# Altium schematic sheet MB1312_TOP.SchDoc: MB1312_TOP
size A4; DocumentNumber: MB1312; Revision: A-03; SheetNumber: 2; SheetTotal: 9; Project: NUCLEO-L4P5ZG
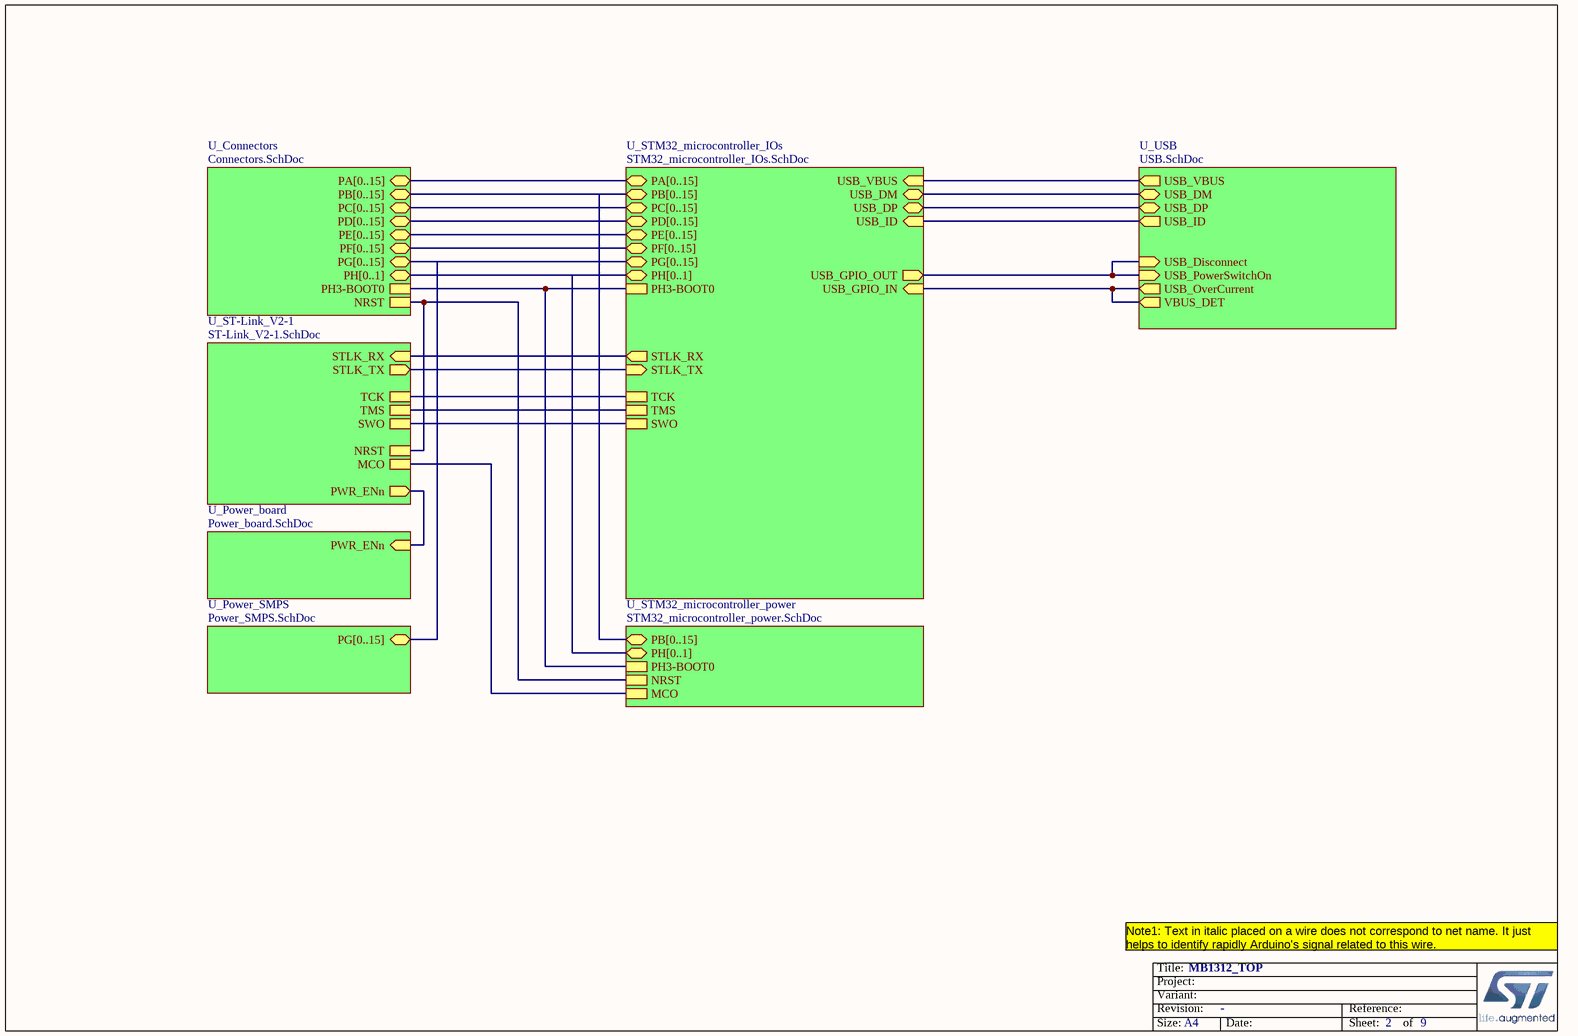
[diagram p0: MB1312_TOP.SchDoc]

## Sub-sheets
U_Connectors = Connectors.SchDoc: PA[0..15] (bidir), PB[0..15] (bidir), PC[0..15] (bidir), NRST, PH3-BOOT0, PD[0..15] (bidir), PE[0..15] (bidir), PF[0..15] (bidir), PG[0..15] (bidir), PH[0..1] (bidir)
U_Power_board = Power_board.SchDoc: PWR_ENn (in)
U_Power_SMPS = Power_SMPS.SchDoc: PG[0..15] (bidir)
U_ST-Link_V2-1 = ST-Link_V2-1.SchDoc: TMS, TCK, MCO, NRST, STLK_RX (in), STLK_TX (out), SWO, PWR_ENn (out)
U_STM32_microcontroller_IOs = STM32_microcontroller_IOs.SchDoc: STLK_TX (in), STLK_RX (out), PA[0..15] (bidir), PB[0..15] (bidir), PC[0..15] (bidir), TCK, TMS, SWO, PD[0..15] (bidir), PE[0..15] (bidir), PF[0..15] (bidir), PG[0..15] (bidir), PH[0..1] (bidir), USB_DM (bidir), USB_DP (bidir), USB_GPIO_OUT (out), USB_GPIO_IN (in), USB_ID (in), USB_VBUS (in), PH3-BOOT0
U_STM32_microcontroller_power = STM32_microcontroller_power.SchDoc: NRST, MCO, PB[0..15] (bidir), PH3-BOOT0, PH[0..1] (bidir)
U_USB = USB.SchDoc: USB_PowerSwitchOn (in), USB_OverCurrent (out), USB_DM (bidir), USB_DP (bidir), USB_ID (out), USB_VBUS (out), USB_Disconnect (in), VBUS_DET (out)

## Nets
(unnamed): sheet U_Connectors/NRST, sheet U_ST-Link_V2-1/NRST, sheet U_STM32_microcontroller_power/NRST
(unnamed): sheet U_Connectors/PH3-BOOT0, sheet U_STM32_microcontroller_IOs/PH3-BOOT0, sheet U_STM32_microcontroller_power/PH3-BOOT0  [a separate net that carries the same name]
(unnamed): sheet U_ST-Link_V2-1/TMS, sheet U_STM32_microcontroller_IOs/TMS  [a separate net that carries the same name]
(unnamed): sheet U_ST-Link_V2-1/TCK, sheet U_STM32_microcontroller_IOs/TCK  [a separate net that carries the same name]
(unnamed): sheet U_ST-Link_V2-1/MCO, sheet U_STM32_microcontroller_power/MCO  [a separate net that carries the same name]
(unnamed): sheet U_ST-Link_V2-1/STLK_RX, sheet U_STM32_microcontroller_IOs/STLK_RX  [a separate net that carries the same name]
(unnamed): sheet U_ST-Link_V2-1/STLK_TX, sheet U_STM32_microcontroller_IOs/STLK_TX  [a separate net that carries the same name]
(unnamed): sheet U_ST-Link_V2-1/SWO, sheet U_STM32_microcontroller_IOs/SWO  [a separate net that carries the same name]
(unnamed): sheet U_ST-Link_V2-1/PWR_ENn, sheet U_Power_board/PWR_ENn  [a separate net that carries the same name]
(unnamed): sheet U_USB/USB_PowerSwitchOn, sheet U_USB/USB_Disconnect, sheet U_STM32_microcontroller_IOs/USB_GPIO_OUT  [a separate net that carries the same name]
(unnamed): sheet U_USB/USB_OverCurrent, sheet U_USB/VBUS_DET, sheet U_STM32_microcontroller_IOs/USB_GPIO_IN  [a separate net that carries the same name]
(unnamed): sheet U_USB/USB_DM, sheet U_STM32_microcontroller_IOs/USB_DM  [a separate net that carries the same name]
(unnamed): sheet U_USB/USB_DP, sheet U_STM32_microcontroller_IOs/USB_DP  [a separate net that carries the same name]
(unnamed): sheet U_USB/USB_ID, sheet U_STM32_microcontroller_IOs/USB_ID  [a separate net that carries the same name]
(unnamed): sheet U_USB/USB_VBUS, sheet U_STM32_microcontroller_IOs/USB_VBUS  [a separate net that carries the same name]

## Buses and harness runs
bus sheet U_Connectors/PA[0..15] = sheet U_STM32_microcontroller_IOs/PA[0..15]
bus sheet U_Connectors/PB[0..15] = sheet U_STM32_microcontroller_IOs/PB[0..15] = sheet U_STM32_microcontroller_power/PB[0..15]
bus sheet U_Connectors/PC[0..15] = sheet U_STM32_microcontroller_IOs/PC[0..15]
bus sheet U_Connectors/PD[0..15] = sheet U_STM32_microcontroller_IOs/PD[0..15]
bus sheet U_Connectors/PE[0..15] = sheet U_STM32_microcontroller_IOs/PE[0..15]
bus sheet U_Connectors/PF[0..15] = sheet U_STM32_microcontroller_IOs/PF[0..15]
bus sheet U_Connectors/PG[0..15] = sheet U_Power_SMPS/PG[0..15] = sheet U_STM32_microcontroller_IOs/PG[0..15]
bus sheet U_Connectors/PH[0..1] = sheet U_STM32_microcontroller_IOs/PH[0..1] = sheet U_STM32_microcontroller_power/PH[0..1]

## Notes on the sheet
- Note1: Text in italic placed on a wire does not correspond to net name. It just helps to identify rapidly Arduino's signal related to this wire.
